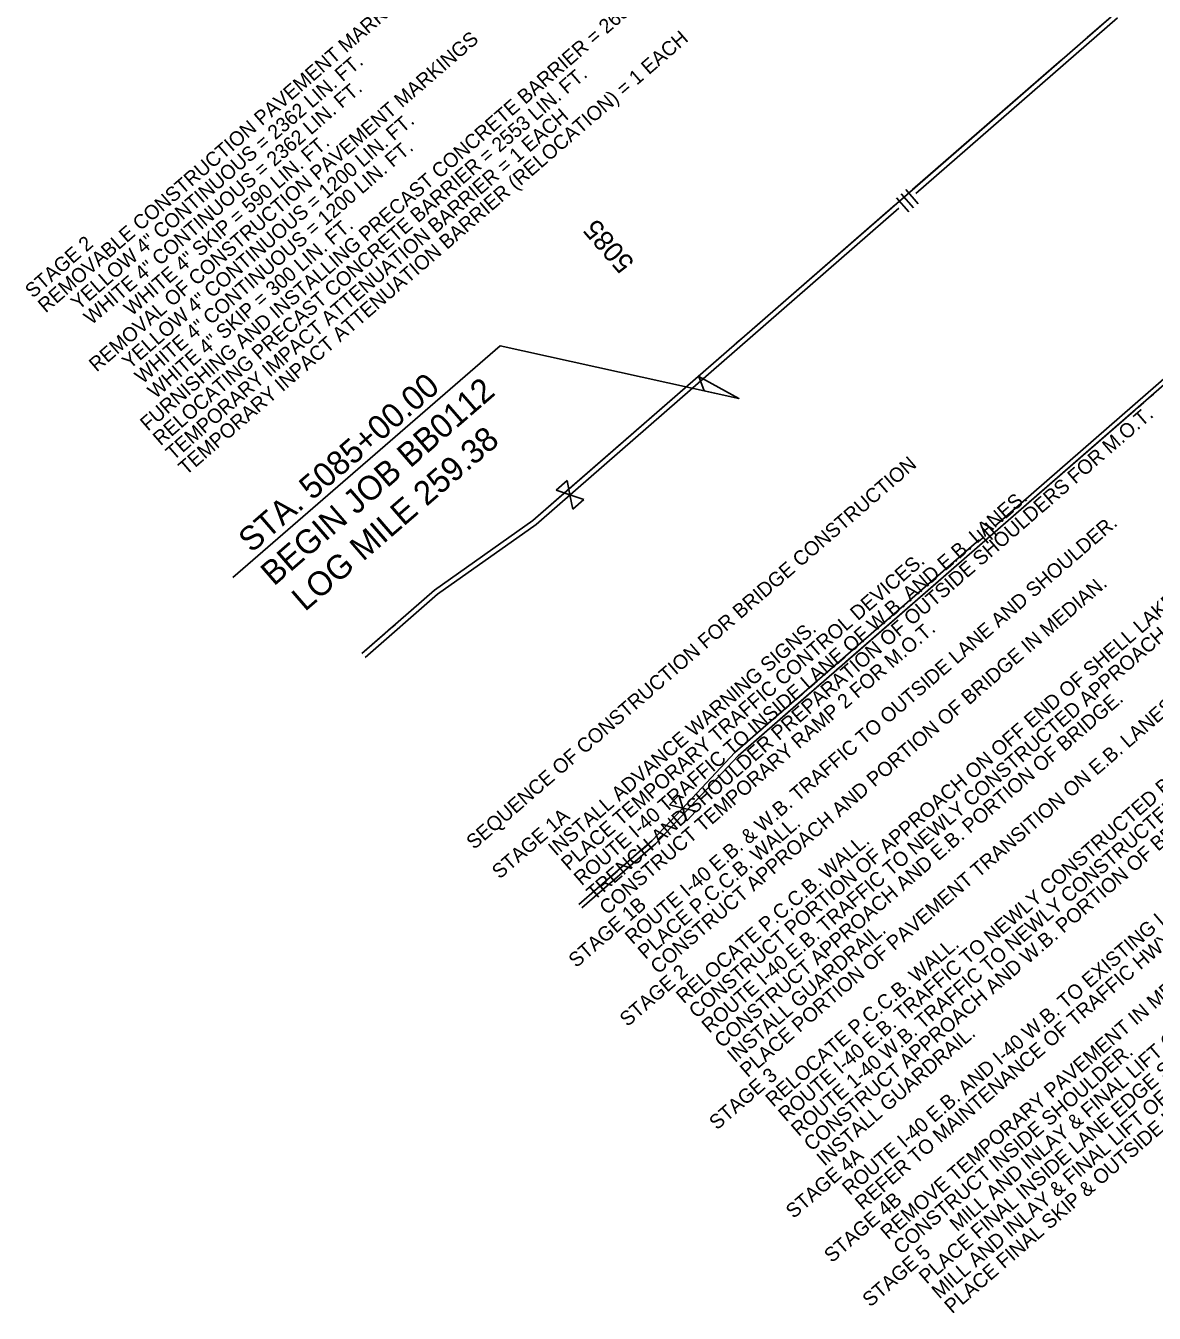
# Model space of a CAD drawing. Extents: x 259983 to 267998, y 211467 to 219827.
# Drawn here: x 261445 to 262385, y 215345 to 216417 of the extents above; entities that cross this region are included whole.
import ezdxf

# ---------------------------------------------------------------- set-up
doc = ezdxf.new("R2010")
doc.units = 0
for name, color, linetype in [('Default', 7, 'Continuous'), ('Level 24', 7, 'Continuous'), ('Level 59', 7, 'Continuous'), ('R-W - CofA', 7, 'Continuous'), ('ROAD', 7, 'Continuous'), ('STATIONING1', 7, 'Continuous')]:
    doc.layers.add(name, color=color, linetype=linetype)

msp = doc.modelspace()

# ---------------------------------------------------------------- linework, layer by layer
at = {"layer": 'Level 24'}
for points in [[(261840, 216150.1), (261617.4, 215957.3)], [(261840, 216150.1), (262038.8, 216106.4)]]:
    msp.add_lwpolyline(points, dxfattribs=at)
at = {"layer": 'Level 59'}
msp.add_lwpolyline([(262010, 216112.7), (262038.8, 216106.4), (262005.5, 216124.5)], close=True, dxfattribs=at)
at = {"layer": 'R-W - CofA'}
for p, q in [((262177.8, 216280.2), (262188.1, 216268.4)), ((262170, 216273.3), (262180.2, 216261.6)), ((262173.9, 216276.8), (262184.2, 216265)), ((261886.5, 216030.1), (261895.7, 216038.1)), ((261895.7, 216038.1), (261898.1, 216026.1)), ((261898.1, 216026.1), (261886.5, 216030.1)), ((261900.4, 216014.1), (261898.1, 216026.1)), ((261898.1, 216026.1), (261909.7, 216022.1)), ((261909.7, 216022.1), (261900.4, 216014.1)), ((262240.6, 215999.8), (262250, 215989)), ((262244.2, 216002.9), (262253.6, 215992.1)), ((262237.1, 215996.6), (262246.4, 215985.9)), ((261981.1, 215767.9), (261988.8, 215776.1)), ((261988.8, 215776.1), (261992.1, 215765.3)), ((261992.1, 215765.3), (261981.1, 215767.9)), ((261995.3, 215754.6), (261992.1, 215765.3)), ((261992.1, 215765.3), (262003, 215762.8)), ((262003, 215762.8), (261995.3, 215754.6))]:
    msp.add_line(p, q, dxfattribs=at)
for points in [[(262328.8, 216406.9), (262348.6, 216424.2), (262277.6, 216549.5)], [(261724.8, 215893.9), (261785.3, 215946.6), (261867.3, 216004.8), (262348.6, 216424.2)], [(262186.1, 216277), (262353.9, 216423.3)], [(262311.2, 216391.6), (262316, 216395.7)], [(262320, 216399.2), (262324.8, 216403.4)], [(262183.4, 216280.2), (262307.2, 216388.1)], [(262045.4, 216159.9), (262169.2, 216267.9)], [(261902.7, 216030.1), (262172, 216264.7)], [(261908.1, 215682.2), (261969.3, 215735.5), (262038.1, 215808.8), (262505.2, 216215.8)], [(262251.8, 216000), (262502.7, 216218.6)], [(262027.8, 216144.7), (262032.6, 216148.8)], [(262036.6, 216152.3), (262041.4, 216156.5)], [(261900, 216033.2), (262023.9, 216141.2)], [(262379.5, 216106.2), (262383.9, 216110)], [(262254.3, 215997.1), (262367.8, 216096)], [(262371.4, 216099.2), (262375.8, 216103)], [(261765.3, 215929.1), (261785.3, 215946.6), (261867.3, 216004.8), (261900, 216033.2)], [(261727.5, 215890.8), (261787.9, 215943.4), (261869.9, 216001.5), (261902.7, 216030.1)], [(261995.9, 215769.4), (262035.5, 215811.5), (262238.9, 215988.7)], [(262127.9, 215887), (262241.4, 215985.9)], [(261756.5, 215921.5), (261761.3, 215925.7)], [(261747.7, 215913.9), (261752.5, 215918)], [(261724.8, 215893.9), (261743.8, 215910.4)], [(262119.9, 215880), (262124.2, 215883.8)], [(261998.7, 215766.8), (262038.1, 215808.8), (262108.2, 215869.8)], [(262111.8, 215873), (262116.2, 215876.8)], [(261905.6, 215685.1), (261966.6, 215738.3), (261995.9, 215769.4)], [(261908.1, 215682.2), (261969.3, 215735.5), (261998.7, 215766.8)]]:
    msp.add_lwpolyline(points, dxfattribs=at)

# ---------------------------------------------------------------- texts
at = {"layer": 'Default'}
for s, p in [('FURNISHING AND INSTALLING PRECAST CONCRETE BARRIER = 2680 LIN. FT.', (261546.7, 216078.7)), ('REMOVABLE CONSTRUCTION PAVEMENT MARKINGS', (261461.6, 216177.1)), ('REMOVAL OF CONSTRUCTION PAVEMENT MARKINGS', (261504.1, 216127.9)), ('TEMPORARY INPACT ATTENUATION BARRIER (RELOCATION) = 1 EACH', (261578.6, 216041.9)), ('     YELLOW 4" CONTINUOUS = 2362 LIN. FT.', (261472.2, 216164.8)), ('RELOCATING PRECAST CONCRETE BARRIER = 2553 LIN. FT.', (261557.3, 216066.4)), ('     WHITE 4" CONTINUOUS = 2362 LIN. FT.', (261482.9, 216152.5)), ('     YELLOW 4" CONTINUOUS = 1200 LIN. FT.', (261514.8, 216115.6)), ('TEMPORARY IMPACT ATTENUATION BARRIER = 1 EACH', (261568, 216054.2)), (' WHITE 4" SKIP = 590 LIN. FT.', (261529.8, 216171.6)), ('     WHITE 4" CONTINUOUS = 1200 LIN. FT.', (261525.4, 216103.3)), ('     WHITE 4" SKIP = 300 LIN. FT.', (261536.1, 216091)), ('STAGE 2', (261450.9, 216189.3))]:
    msp.add_text(s, height=12, rotation=40.8833, dxfattribs=at).set_placement(p)
at = {"layer": 'Level 24'}
for s, p in [('STA. 5085+00.00', (261633, 215977.2)), ('BEGIN JOB BB0112', (261651.6, 215949.6)), ('LOG MILE 259.38', (261677.5, 215928.4))]:
    msp.add_text(s, height=20, rotation=40.8833, dxfattribs=at).set_placement(p)
at = {"layer": 'ROAD'}
for s, p in [('CONSTRUCT PORTION OF APPROACH ON OFF END OF SHELL LAKE BRIDGE PRIOR TO SHIFTING OF TRAFFIC.', (262003.6, 215589.6)), ('TRENCH AND SHOULDER PREPARATION OF OUTSIDE SHOULDERS FOR M.O.T.', (261918.4, 215687.9)), ('SEQUENCE OF CONSTRUCTION FOR BRIDGE CONSTRUCTION', (261818.3, 215730.3)), ('ROUTE I-40 E.B. TRAFFIC TO NEWLY CONSTRUCTED APPROACH AND BRIDGE IN MEDIAN.', (262014.2, 215577.3)), ('PLACE PORTION OF PAVEMENT TRANSITION ON E.B. LANES UTILIZING ONE LANE OF TRAFFIC.', (262046.1, 215540.5)), ('ROUTE I-40 TRAFFIC TO INSIDE LANE OF W.B. AND E.B. LANES.', (261907.8, 215700.2)), ('ROUTE I-40 E.B. & W.B. TRAFFIC TO OUTSIDE LANE AND SHOULDER.', (261950.4, 215651.1)), ('PLACE TEMPORARY TRAFFIC CONTROL DEVICES.', (261897.2, 215712.5)), ('CONSTRUCT APPROACH AND PORTION OF BRIDGE IN MEDIAN.', (261971.6, 215626.5)), ('ROUTE I-40 E.B. TRAFFIC TO NEWLY CONSTRUCTED BRIDGE AND EXISTING E.B. LANES.', (262078, 215503.6)), ('ROUTE 1-40 W.B. TRAFFIC TO NEWLY CONSTRUCTED APPROACH AND BRIDGE IN MEDIAN.', (262088.7, 215491.3)), ('REFER TO MAINTENANCE OF TRAFFIC HWY. 149 INTERCHANGE RAMP RECONSTRUCTION SHEETS.', (262141.9, 215429.9)), ('INSTALL ADVANCE WARNING SIGNS.', (261886.5, 215724.8)), ('CONSTRUCT TEMPORARY RAMP 2 FOR M.O.T.', (261929.1, 215675.7)), ('CONSTRUCT APPROACH AND E.B. PORTION OF BRIDGE.', (262024.8, 215565)), ('CONSTRUCT APPROACH AND W.B. PORTION OF BRIDGE.', (262099.3, 215479)), ('STAGE 1A', (261839.6, 215705.7)), ('PLACE P.C.C.B. WALL.', (261961, 215638.8)), ('RELOCATE P.C.C.B. WALL.', (261992.9, 215601.9)), ('ROUTE I-40 E.B. AND I-40 W.B. TO EXISTING LANES.', (262131.2, 215442.2)), ('STAGE 1B', (261903.4, 215631.9)), ('INSTALL GUARDRAIL.', (262035.5, 215552.8)), ('MILL AND INLAY & FINAL LIFT OF INSIDE LANES.', (262220.7, 215412.1)), ('RELOCATE P.C.C.B. WALL.', (262067.4, 215515.9)), ('REMOVE TEMPORARY PAVEMENT IN MEDIAN.', (262163.1, 215405.3)), ('STAGE 2', (261946, 215582.8)), ('MILL AND INLAY & FINAL LIFT OF OUTSIDE LANES.', (262205.7, 215356.1)), ('PLACE FINAL SKIP & OUTSIDE LANE EDGE STRIPING.', (262216.3, 215343.8)), ('PLACE FINAL INSIDE LANE EDGE STRIPING.', (262195.1, 215368.4)), ('INSTALL GUARDRAIL.', (262110, 215466.7)), ('CONSTRUCT INSIDE SHOULDER.', (262173.8, 215393)), ('STAGE 3', (262020.5, 215496.8)), ('STAGE 4A', (262084.3, 215423)), ('STAGE 4B', (262116.2, 215386.2)), ('STAGE 5', (262148.1, 215349.3))]:
    msp.add_text(s, height=12, rotation=40.8833, dxfattribs=at).set_placement(p)
at = {"layer": 'STATIONING1'}
msp.add_text('5085', height=16.5, rotation=130.8833, dxfattribs=at).set_placement((261952.5, 216219.8))

doc.saveas('drawing.dxf')
